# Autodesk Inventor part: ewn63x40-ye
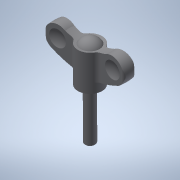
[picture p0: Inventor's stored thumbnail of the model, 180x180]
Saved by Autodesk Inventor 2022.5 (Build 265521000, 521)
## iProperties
Created: 2017-05
Part Number: ewn63x40-ye
Material: 一般
Document SubType Name: Modeling
Designer: imaocorp
Density: 1 g/cm^3
Appearance: 既定
Author: imaocorp
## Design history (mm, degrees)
node "ewn63x40-ye.x_t1"
node "ewn63x40-ye"
node "Base1"
